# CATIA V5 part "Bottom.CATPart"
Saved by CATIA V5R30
Part number: Plate
Bounding box of the stored display mesh (mm): x -85 to 85, y -84.802 to 84.802, z 0 to 10
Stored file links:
  D:\PROJECTS\CATIA V56R 2020\Resources\Parts File\c12_catia_v5_6r2020_prt\c12_catia_v5-6r2020 figr_12-30\Bottom.CATPart
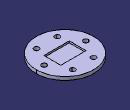
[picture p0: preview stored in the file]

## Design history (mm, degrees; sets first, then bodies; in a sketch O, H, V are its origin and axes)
Body1 (main body)
  Sketch1 on xy-plane, origin (0, 0, 0), H (1, 0, 0), V (0, 1, 0)
    circle A1 centre (0, 0) radius 85
    line L1 (37.5, 25) -> (37.5, -25)
    line L2 (37.5, -25) -> (-37.5, -25)
    line L3 (-37.5, -25) -> (-37.5, 25)
    line L4 (-37.5, 25) -> (37.5, 25)
    length L2 = 75
    length L1 = 50
    radius A1 = 85
    vertical: L1 V, L3 V
    horizontal: L2 H, L4 H
    equidistance: L1 L3 O, L2 L4 O
  MultiPad1: profile Sketch1, domains (length 5; length 10)
  Sketch2 on face of MultiPad1, origin (0, 0, 10), H (1, 0, 0), V (0, 1, 0)
    circle A1 centre (62, 0) radius 7.5
    point P1 (62, 0)
    radius A1 = 7.5
    distance P1 V = 62
    coincidence: P1 H
  Pocket1: profile Sketch2, direction (0, 0, -1), through (limit type 6)
  CircPattern1: of Pocket1, instances 6, angular step 60 {= 360.0*1 deg/CircPattern1.AngularNumber}, axis from xy-plane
